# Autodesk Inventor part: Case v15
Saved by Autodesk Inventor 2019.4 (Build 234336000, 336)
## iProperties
Created: 2020-01
Part Number: Case v15
Material: Generic
Document SubType Name: Modeling
Designer: Administrator
Density: 1 g/cm^3
Appearance: Default
Author: Administrator
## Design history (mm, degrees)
feature "Body1"
feature "Body2"
feature "Body3"
feature "Body5"
body "Solid1"
body "Solid2"
body "Solid3"
body "Solid4"
